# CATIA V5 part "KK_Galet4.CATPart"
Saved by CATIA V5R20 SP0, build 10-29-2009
Part number: Galet4
Bounding box of the stored display mesh (mm): x 9 to 13.5, y 225.003 to 244.997, z -24.997 to -5.003
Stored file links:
  G:\Khaled_CFAO_2011\ST2M\ST2M_GR2\aandujar\Khaled\CAD_thinkMOTION\KK_Galet4.CATPart
  G:\Khaled_CFAO_2011\ST2M\ST2M_GR2\aandujar\Khaled\CAD_thinkMOTION\KK_Aandujar.CATProduct
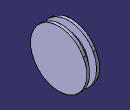
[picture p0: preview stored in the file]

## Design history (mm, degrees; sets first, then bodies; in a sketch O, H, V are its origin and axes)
WSupportSet1: ActiveGrid {3dwsupport RefPoint {point stored without definition}, 3DWOS ({wsupport Support xy-plane, RefPoint {3dwsupport}, GridIn {cartgrid Value 100, Stepbid1 0, Value 100, Stepbid2 0, Direction (1, 0, 0)}, GeometricData ({line type PtDir, Direction (1, 0, 0), Support xy-plane}; {line type PtDir, Direction (0, 1, 0), Support yz-plane})}; {wsupport Support yz-plane, RefPoint {3dwsupport}, GridIn {cartgrid Value 100, Stepbid1 0, Value 100, Stepbid2 0, Direction (0, 1, 0)}, GeometricData ({line type PtDir, Direction (0, 1, 0), Support yz-plane}; {line type PtDir, Direction (0, 0, 1), Support zx-plane})}; {wsupport Support zx-plane, RefPoint {3dwsupport}, GridIn {cartgrid Value 100, Stepbid1 0, Value 100, Stepbid2 0, Direction (0, 0, 1)}, GeometricData ({line type PtDir, Direction (0, 0, 1), Support zx-plane}; {line type PtDir, Direction (1, 0, 0), Support xy-plane})}), GeometricData ({line type PtDir, RefPoint {point stored without definition}, Direction (1, 0, 0), Support xy-plane}; {line type PtDir, RefPoint {point stored without definition}, Direction (0, 1, 0), Support yz-plane}; {line type PtDir, RefPoint {point stored without definition}, Direction (0, 0, 1), Support zx-plane})}
Set1
  Plane1: stored without definition
  Sketch1 on Plane1, origin (0, 0, -15), H (1, 0, 0), V (0, 1, 0)
    line L1 (9, 235) -> (13.5, 235)
    line L2 (13.5, 235) -> (13.5, 225)
    line L3 (13.5, 225) -> (12.5, 225)
    point P4 (12.5, 225)
    line L4 (12.5, 225) -> (12.5, 228)
    line L5 (12.5, 228) -> (10, 228)
    line L6 (10, 228) -> (10, 225)
    point P7 (10, 225)
    line L7 (10, 225) -> (9, 225)
    line L8 (9, 225) -> (9, 235)
    reference projected line E1 (-7.5, 235) -> (32.5, 235) from Line1
    reference intersected line E2 through (12.5, 0) direction (0, 1) from Plane2
    distance L2 L4 = 1
    distance L8 L6 = 1
    distance L4 L6 = 2.5
    distance L1 L5 = 7
    distance L1 P4 = 10
    horizontal: L1 H, L3 H, L5 H, L7 H
    vertical: L2 V, L4 V, L6 V, L8 V
    coincidence: P7 L3, L1 E1, L4 E2
Set2
  Line1 "Axe_pivot_galet4": linked copy from another document
  Plane2 "Plan.Ref5": linked copy from another document
Body1 (main body)
  Shaft1: profile Sketch1, axis Line1, angle 360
